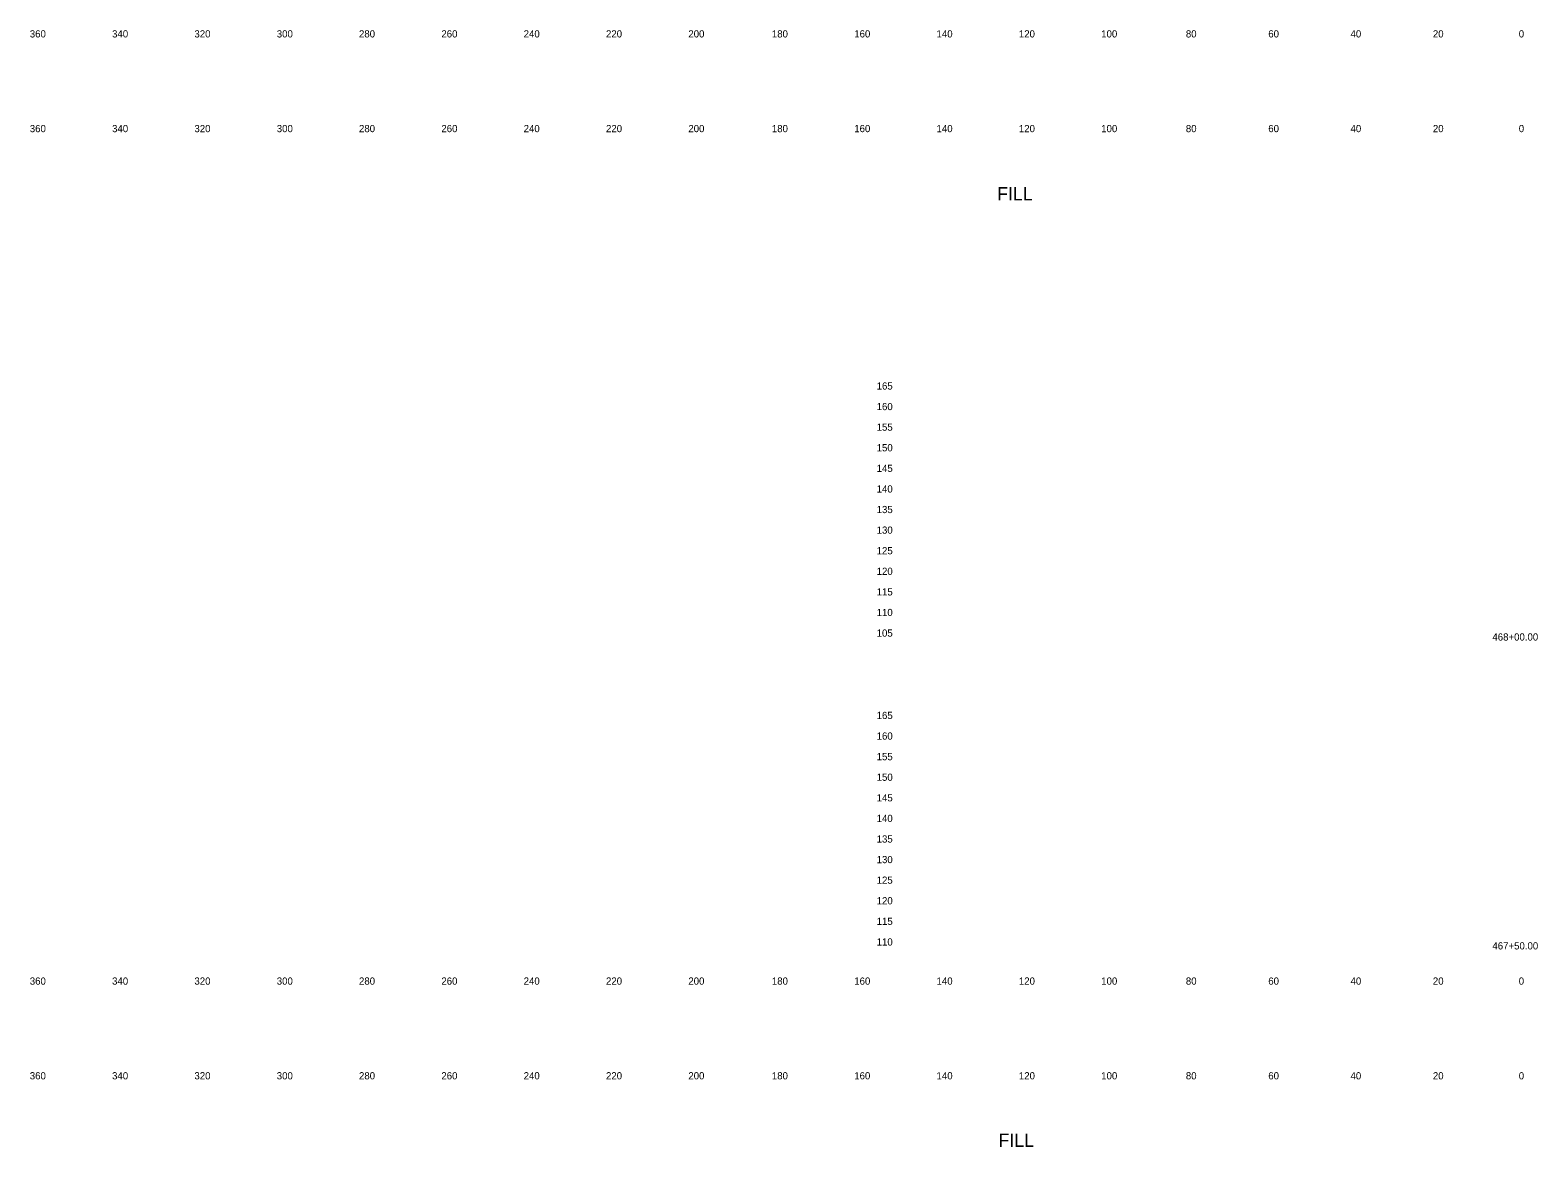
# Model space of a CAD drawing. Extents: x 21281 to 22024, y 6472 to 15198.
# Drawn here: x 21280.5 to 21646.7, y 9196 to 9467.1 of the extents above; entities that cross this region are included whole.
import ezdxf

# ---------------------------------------------------------------- set-up
doc = ezdxf.new("R2010")
doc.units = 0
for name, color, linetype in [('XS_SHEET_LABELS_ELEVATION', 7, 'Continuous'), ('XS_SHEET_LABELS_OFFSET', 7, 'Continuous'), ('XS_SHEET_LABELS_STATION', 7, 'Continuous')]:
    doc.layers.add(name, color=color, linetype=linetype)

msp = doc.modelspace()

# ---------------------------------------------------------------- texts
at = {"layer": 'XS_SHEET_LABELS_ELEVATION'}
for s, p in [('  165  ', (21484.84, 9379.84)), ('  160  ', (21484.84, 9374.84)), ('  155  ', (21484.84, 9369.84)), ('  150  ', (21484.84, 9364.84)), ('  145  ', (21484.84, 9359.84)), ('  140  ', (21484.84, 9354.84)), ('  135  ', (21484.84, 9349.84)), ('  130  ', (21484.84, 9344.84)), ('  125  ', (21484.84, 9339.84)), ('  120  ', (21484.84, 9334.84)), ('  115  ', (21484.84, 9329.84)), ('  110  ', (21484.84, 9324.84)), ('  105  ', (21484.84, 9319.84)), ('  165  ', (21484.84, 9299.84)), ('  160  ', (21484.84, 9294.84)), ('  155  ', (21484.84, 9289.84)), ('  150  ', (21484.84, 9284.84)), ('  145  ', (21484.84, 9279.84)), ('  140  ', (21484.84, 9274.84)), ('  135  ', (21484.84, 9269.84)), ('  130  ', (21484.84, 9264.84)), ('  125  ', (21484.84, 9259.84)), ('  120  ', (21484.84, 9254.84)), ('  115  ', (21484.84, 9249.84)), ('  110  ', (21484.84, 9244.84))]:
    msp.add_text(s, height=1.75, dxfattribs=at).set_placement(p)
at = {"layer": 'XS_SHEET_LABELS_OFFSET'}
for s, height, p in [('  360  ', 1.75, (21279.14, 9465.34)), ('  340  ', 1.75, (21299.13, 9465.34)), ('  320  ', 1.75, (21319.13, 9465.34)), ('  300  ', 1.75, (21339.13, 9465.34)), ('  280  ', 1.75, (21359.1, 9465.34)), ('  260  ', 1.75, (21379.11, 9465.34)), ('  240  ', 1.75, (21399.1, 9465.34)), ('  220  ', 1.75, (21419.1, 9465.34)), ('  200  ', 1.75, (21439.1, 9465.34)), ('  180  ', 1.75, (21459.39, 9465.34)), ('  160  ', 1.75, (21479.4, 9465.34)), ('  140  ', 1.75, (21499.39, 9465.34)), ('  120  ', 1.75, (21519.39, 9465.34)), ('  100  ', 1.75, (21539.39, 9465.34)), ('  80  ', 1.75, (21559.95, 9465.34)), ('  60  ', 1.75, (21579.97, 9465.34)), ('  40  ', 1.75, (21599.95, 9465.34)), ('  20  ', 1.75, (21619.95, 9465.34)), ('  0  ', 1.75, (21640.81, 9465.34)), ('  0  ', 1.75, (21640.81, 9465.34)), ('  360  ', 1.75, (21279.14, 9442.34)), ('  340  ', 1.75, (21299.13, 9442.34)), ('  320  ', 1.75, (21319.13, 9442.34)), ('  300  ', 1.75, (21339.13, 9442.34)), ('  280  ', 1.75, (21359.1, 9442.34)), ('  260  ', 1.75, (21379.11, 9442.34)), ('  240  ', 1.75, (21399.1, 9442.34)), ('  220  ', 1.75, (21419.1, 9442.34)), ('  200  ', 1.75, (21439.1, 9442.34)), ('  180  ', 1.75, (21459.39, 9442.34)), ('  160  ', 1.75, (21479.4, 9442.34)), ('  140  ', 1.75, (21499.39, 9442.34)), ('  120  ', 1.75, (21519.39, 9442.34)), ('  100  ', 1.75, (21539.39, 9442.34)), ('  80  ', 1.75, (21559.95, 9442.34)), ('  60  ', 1.75, (21579.97, 9442.34)), ('  40  ', 1.75, (21599.95, 9442.34)), ('  20  ', 1.75, (21619.95, 9442.34)), ('  0  ', 1.75, (21640.81, 9442.34)), ('  0  ', 1.75, (21640.81, 9442.34)), ('FILL', 3.222, (21515.4, 9425.79)), ('  360  ', 1.75, (21279.14, 9235.34)), ('  340  ', 1.75, (21299.13, 9235.34)), ('  320  ', 1.75, (21319.13, 9235.34)), ('  300  ', 1.75, (21339.13, 9235.34)), ('  280  ', 1.75, (21359.1, 9235.34)), ('  260  ', 1.75, (21379.11, 9235.34)), ('  240  ', 1.75, (21399.1, 9235.34)), ('  220  ', 1.75, (21419.1, 9235.34)), ('  200  ', 1.75, (21439.1, 9235.34)), ('  180  ', 1.75, (21459.39, 9235.34)), ('  160  ', 1.75, (21479.4, 9235.34)), ('  140  ', 1.75, (21499.39, 9235.34)), ('  120  ', 1.75, (21519.39, 9235.34)), ('  100  ', 1.75, (21539.39, 9235.34)), ('  80  ', 1.75, (21559.95, 9235.34)), ('  60  ', 1.75, (21579.97, 9235.34)), ('  40  ', 1.75, (21599.95, 9235.34)), ('  20  ', 1.75, (21619.95, 9235.34)), ('  0  ', 1.75, (21640.81, 9235.34)), ('  0  ', 1.75, (21640.81, 9235.34)), ('  360  ', 1.75, (21279.14, 9212.34)), ('  340  ', 1.75, (21299.13, 9212.34)), ('  320  ', 1.75, (21319.13, 9212.34)), ('  300  ', 1.75, (21339.13, 9212.34)), ('  280  ', 1.75, (21359.1, 9212.34)), ('  260  ', 1.75, (21379.11, 9212.34)), ('  240  ', 1.75, (21399.1, 9212.34)), ('  220  ', 1.75, (21419.1, 9212.34)), ('  200  ', 1.75, (21439.1, 9212.34)), ('  180  ', 1.75, (21459.39, 9212.34)), ('  160  ', 1.75, (21479.4, 9212.34)), ('  140  ', 1.75, (21499.39, 9212.34)), ('  120  ', 1.75, (21519.39, 9212.34)), ('  100  ', 1.75, (21539.39, 9212.34)), ('  80  ', 1.75, (21559.95, 9212.34)), ('  60  ', 1.75, (21579.97, 9212.34)), ('  40  ', 1.75, (21599.95, 9212.34)), ('  20  ', 1.75, (21619.95, 9212.34)), ('  0  ', 1.75, (21640.81, 9212.34)), ('  0  ', 1.75, (21640.81, 9212.34)), ('FILL', 3.222, (21515.74, 9195.96))]:
    msp.add_text(s, height=height, dxfattribs=at).set_placement(p)
at = {"layer": 'XS_SHEET_LABELS_STATION'}
for s, p in [('  468+00.00  ', (21634.41, 9318.89)), ('  467+50.00  ', (21634.41, 9243.89))]:
    msp.add_text(s, height=1.75, dxfattribs=at).set_placement(p)

doc.saveas('drawing.dxf')
